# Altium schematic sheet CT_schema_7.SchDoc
size 369 x 243 mm
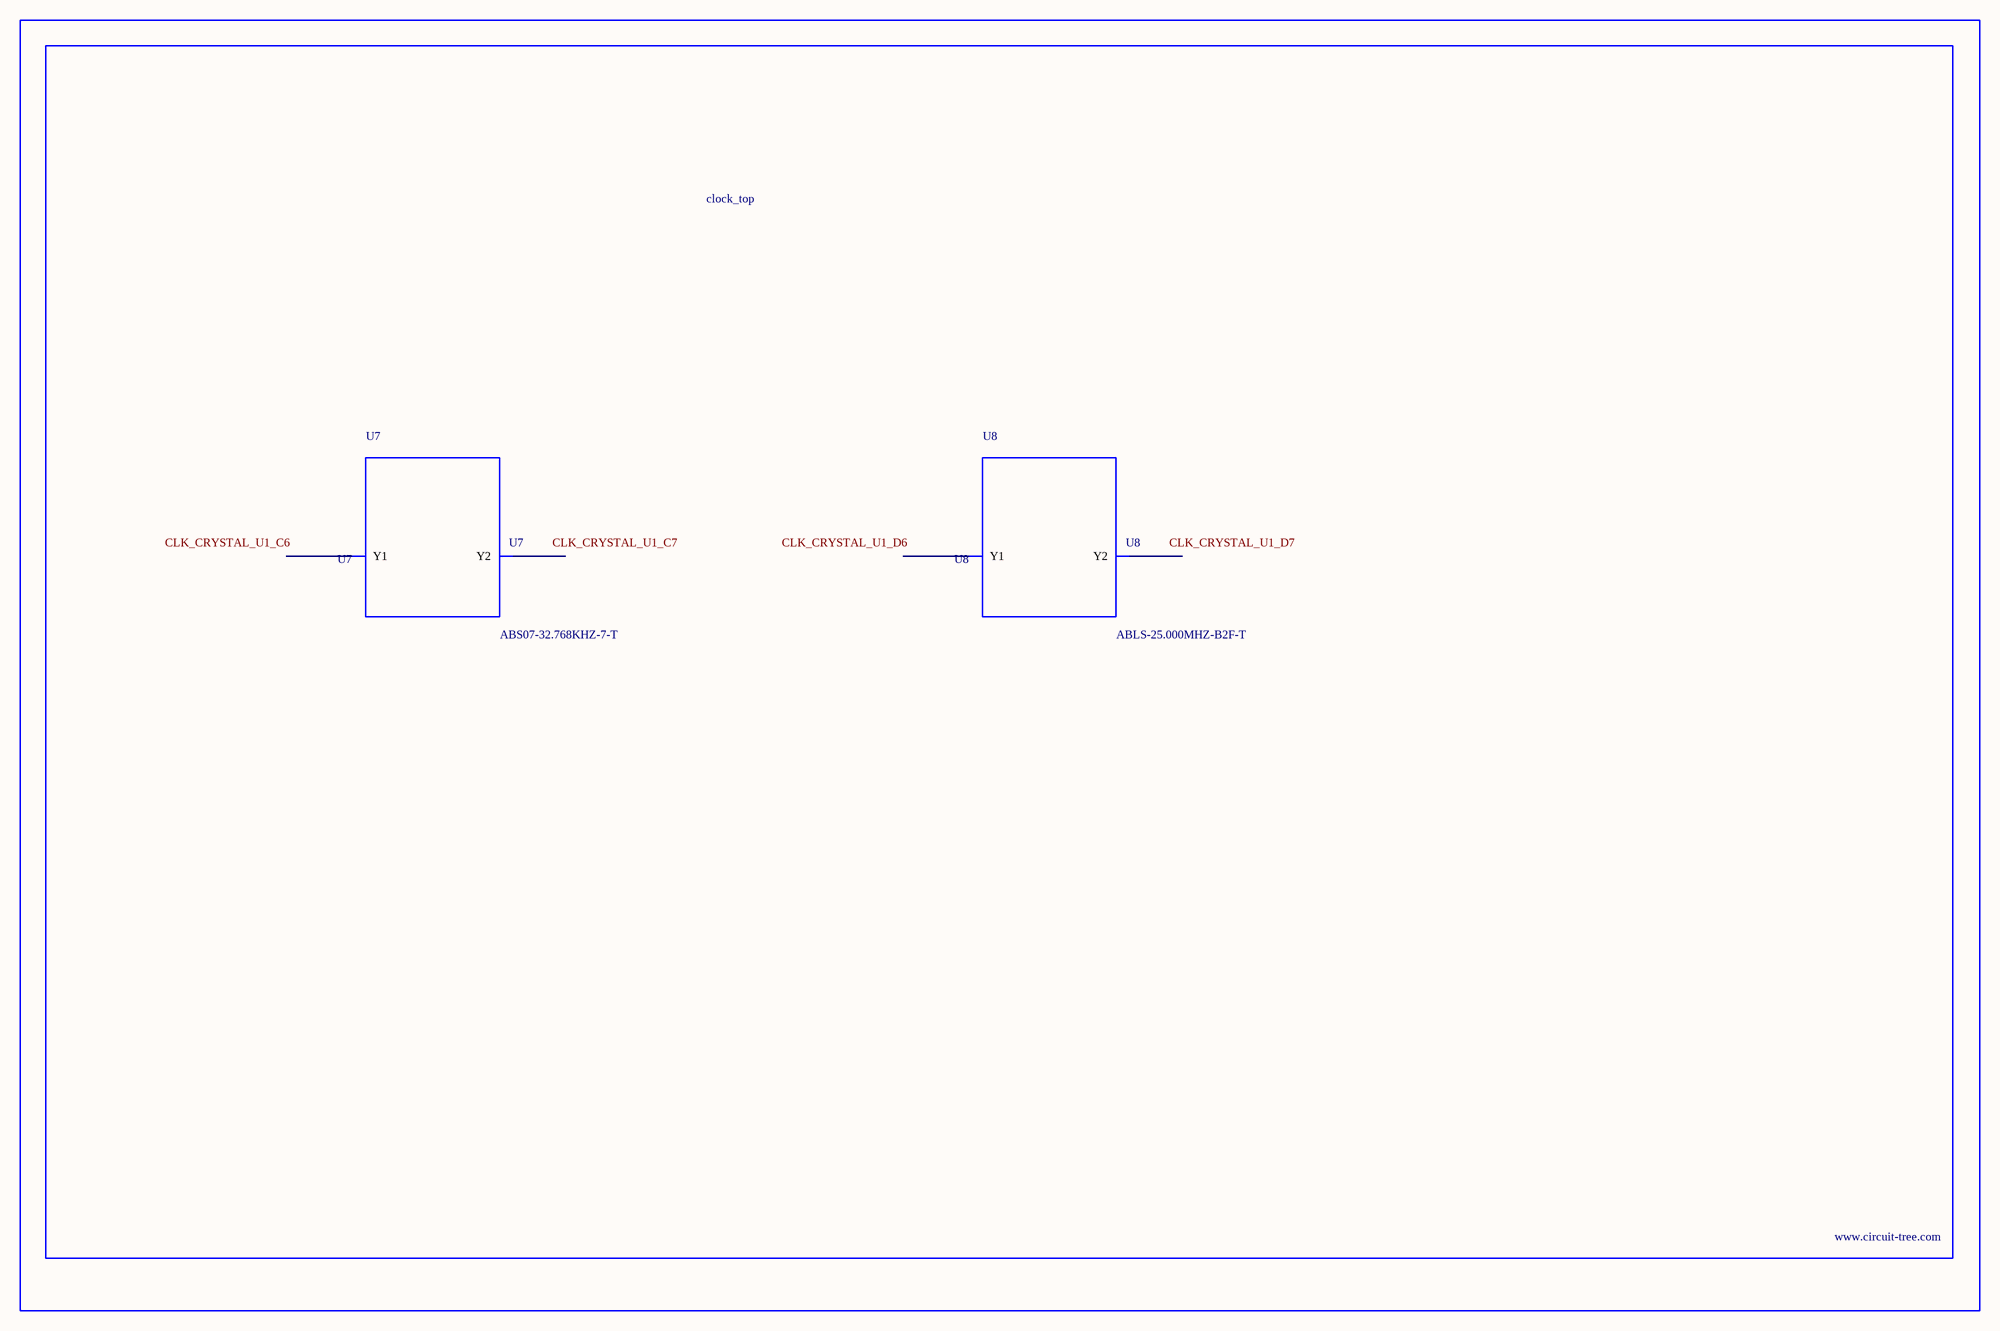
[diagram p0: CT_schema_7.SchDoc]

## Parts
BORDER6  (no value)
U7  ABS07-32.768KHZ-7-T  [ABS07-32.768KHZ-7-T]
U8  ABLS-25.000MHZ-B2F-T  [ABLS-25.000MHZ-B2F-T]

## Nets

Not connected (* = marked no-connect by the designer): U7 1(Y1) 2(Y2); U8 1(Y1) 2(Y2)

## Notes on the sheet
- Labels drawn without touching a wire or pin: CLK_CRYSTAL_U1_C6, CLK_CRYSTAL_U1_C7, CLK_CRYSTAL_U1_D6, CLK_CRYSTAL_U1_D7

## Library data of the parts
BORDER6 = BORDER_PAGE6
